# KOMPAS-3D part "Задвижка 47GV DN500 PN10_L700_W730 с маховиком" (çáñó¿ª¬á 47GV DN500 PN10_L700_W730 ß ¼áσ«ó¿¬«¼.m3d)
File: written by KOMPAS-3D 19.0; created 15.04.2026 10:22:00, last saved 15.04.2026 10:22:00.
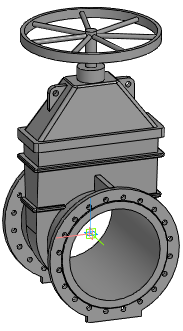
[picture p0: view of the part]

Document properties: Автор: Евгений; Полное имя файла: Z:\3.Личные\kachalov\3d для проектировщиков\2.1 Тип 47GV, 47GV.Z\Задвижка 47GV_DN40-DN600\stp_Задвижка 47GV\Задвижка 47GV DN500 PN10_L700_W730 с маховиком.m3d

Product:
- Part/product: Задвижка 47GV DN500 PN10_L700_W730 с маховиком

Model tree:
1. Операция без истории:1  (labels: Задвижка 47GV DN500 PN10_L700_W730 с маховиком)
